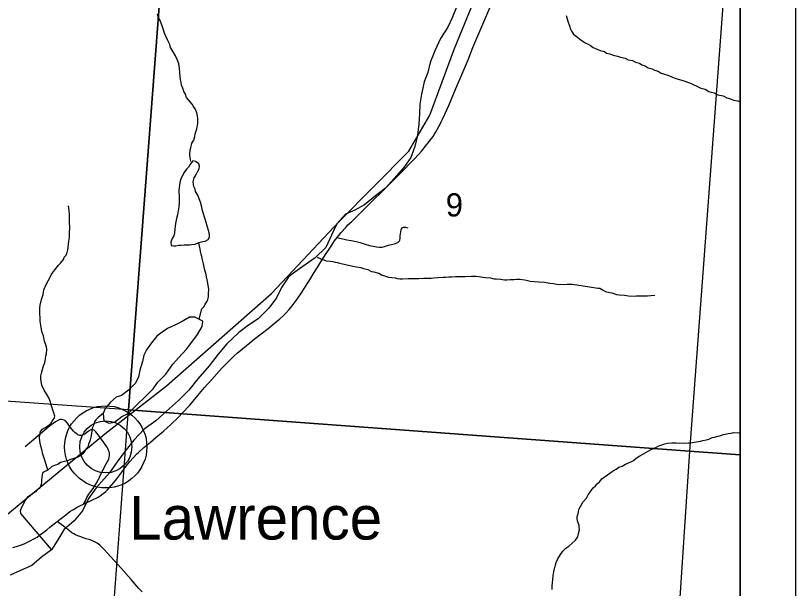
# Model space of a CAD drawing. Extents: x 0 to 82.7, y -0.2 to 22.
# Drawn here: x 7.589 to 9, y 17.868 to 18.905 of the extents above; entities that cross this region are included whole.
import ezdxf

# ---------------------------------------------------------------- set-up
doc = ezdxf.new("R2010")
doc.units = 0
for name, color, linetype in [('GM_X_County_Road', 7, 'Continuous'), ('GM_X_Minor_Lake', 7, 'Continuous'), ('GM_X_Minor_River', 7, 'Continuous'), ('GM_X_Rail_Line', 7, 'Continuous'), ('GM_X_Section', 7, 'Continuous'), ('GM_X_Section_Text', 7, 'Continuous'), ('GM_X_State_Route', 7, 'Continuous'), ('GM_X_Township_Road', 7, 'Continuous'), ('GM_X_Township_Text', 7, 'Continuous'), ('GM_X_Unincorporated', 7, 'Continuous'), ('GM_X_Unincorporated_Location', 7, 'Continuous'), ('GM_X_Unincorporated_Text', 7, 'Continuous'), ('SH_Cut_Line', 7, 'Continuous'), ('SH_Data', 7, 'Continuous')]:
    doc.layers.add(name, color=color, linetype=linetype)

msp = doc.modelspace()

# ---------------------------------------------------------------- linework, layer by layer
at = {"layer": 'GM_X_County_Road'}
for points in [[(8.9, 18.1099), (8.9, 19.1246), (8.8838, 19.1258), (8.8083, 18.1167)], [(8.9, 17.1004), (8.9, 18.1099), (8.8083, 18.1167), (8.7418, 17.1109)]]:
    msp.add_lwpolyline(points, close=True, dxfattribs=at)
at = {"layer": 'GM_X_Minor_Lake'}
for points in [[(7.9276, 18.3519), (7.9132, 18.3595), (7.9033, 18.3591), (7.8904, 18.3515), (7.8778, 18.3458), (7.8638, 18.3386), (7.8539, 18.3325), (7.8444, 18.3249), (7.8345, 18.3132), (7.8257, 18.3002), (7.8208, 18.2907), (7.8181, 18.2793), (7.8135, 18.2634), (7.8109, 18.2508), (7.8048, 18.2391), (7.793, 18.2273), (7.7804, 18.2174), (7.7706, 18.2144), (7.7603, 18.2056), (7.7508, 18.1943), (7.7474, 18.1848), (7.7481, 18.1718), (7.7576, 18.1676), (7.7679, 18.1695), (7.7808, 18.1798), (7.7926, 18.1851), (7.807, 18.1995), (7.8245, 18.2166), (7.8375, 18.2299), (7.8462, 18.2417), (7.8603, 18.2561), (7.8732, 18.274), (7.8835, 18.2858), (7.8979, 18.3013), (7.9094, 18.3165), (7.9181, 18.3283), (7.9261, 18.3424), (7.9276, 18.3519)], [(7.7603, 18.2056), (7.7508, 18.1943), (7.7474, 18.1848), (7.7481, 18.1718), (7.7576, 18.1676), (7.7679, 18.1695), (7.7808, 18.1798), (7.7926, 18.1851), (7.807, 18.1995), (7.8245, 18.2166), (7.8375, 18.2299), (7.8462, 18.2417), (7.8603, 18.2561), (7.8732, 18.274), (7.8835, 18.2858), (7.8979, 18.3013), (7.9094, 18.3165), (7.9181, 18.3283), (7.9261, 18.3424), (7.9276, 18.3519)], [(7.9276, 18.3519), (7.9132, 18.3595), (7.9033, 18.3591), (7.8904, 18.3515), (7.8778, 18.3458), (7.8638, 18.3386), (7.8539, 18.3325), (7.8444, 18.3249), (7.8345, 18.3132), (7.8257, 18.3002), (7.8208, 18.2907), (7.8181, 18.2793), (7.8135, 18.2634), (7.8109, 18.2508), (7.8048, 18.2391), (7.793, 18.2273), (7.7804, 18.2174), (7.7706, 18.2144), (7.7603, 18.2056)]]:
    msp.add_lwpolyline(points, dxfattribs=at)
at = {"layer": 'GM_X_Minor_River'}
for points in [[(8.3867, 18.9205), (8.3786, 18.9016), (8.3709, 18.8845), (8.3579, 18.8641), (8.3475, 18.8417), (8.3387, 18.8205), (8.3348, 18.8027), (8.3282, 18.7856), (8.3231, 18.7629), (8.3203, 18.7451), (8.3198, 18.7276), (8.3186, 18.7097), (8.3158, 18.6881), (8.3115, 18.6684), (8.3038, 18.6487), (8.2911, 18.6305), (8.2739, 18.6105), (8.2579, 18.5931), (8.24, 18.5792), (8.2201, 18.5629), (8.2026, 18.5532), (8.1855, 18.546), (8.1702, 18.5286), (8.1606, 18.5078), (8.1502, 18.4858), (8.1311, 18.4666), (8.1022, 18.447), (8.0831, 18.433), (8.0701, 18.413), (8.0609, 18.3944), (8.0471, 18.3755), (8.0276, 18.3566), (8.0101, 18.3449), (7.9926, 18.3314), (7.9712, 18.3114), (7.9555, 18.2921), (7.9387, 18.2713), (7.9184, 18.2478), (7.902, 18.2274), (7.8837, 18.2082), (7.8619, 18.1889), (7.8425, 18.1719), (7.8215, 18.1565), (7.8024, 18.1368), (7.7887, 18.1194), (7.7737, 18.099), (7.7588, 18.0778), (7.7347, 18.0502), (7.7206, 18.0309), (7.7098, 18.0086), (7.6949, 17.9904), (7.6762, 17.9742), (7.6651, 17.956), (7.6536, 17.9379), (7.6353, 17.925), (7.6181, 17.9099), (7.5976, 17.9006), (7.5789, 17.8923)], [(7.906, 18.6412), (7.9046, 18.6484), (7.9039, 18.6533), (7.9043, 18.6621), (7.9059, 18.6659), (7.9079, 18.6742), (7.911, 18.6802), (7.913, 18.6863), (7.9138, 18.6912), (7.9165, 18.7003), (7.9182, 18.7102), (7.9186, 18.7147), (7.9187, 18.7197), (7.9179, 18.7235), (7.9169, 18.7296), (7.9135, 18.7368), (7.9106, 18.7407), (7.908, 18.7452), (7.9016, 18.7529), (7.8978, 18.7572), (7.896, 18.7629), (7.8934, 18.7682), (7.8916, 18.774), (7.889, 18.7797), (7.8883, 18.7842), (7.8868, 18.79), (7.8865, 18.7953), (7.8858, 18.8018), (7.8852, 18.8101), (7.8841, 18.8181), (7.8812, 18.8258), (7.8779, 18.8326), (7.8738, 18.8399), (7.8689, 18.8479), (7.8675, 18.8533), (7.8638, 18.8617), (7.8604, 18.8682), (7.8582, 18.8735), (7.856, 18.8815), (7.852, 18.8915), (7.8498, 18.8976), (7.8475, 18.9014), (7.8457, 18.9083)], [(8.5851, 18.9057), (8.5884, 18.8954), (8.5913, 18.887), (8.5928, 18.8809), (8.5946, 18.8771), (8.5984, 18.8721), (8.6055, 18.8663), (8.61, 18.8625), (8.6194, 18.8563), (8.6251, 18.8535), (8.6292, 18.8516), (8.6341, 18.8477), (8.6383, 18.8458), (8.6466, 18.8423), (8.6542, 18.8403), (8.6583, 18.8375), (8.6644, 18.8363), (8.67, 18.8336), (8.678, 18.832), (8.6836, 18.83), (8.6916, 18.8284), (8.6976, 18.8253), (8.7052, 18.824), (8.7108, 18.8213), (8.7176, 18.8193), (8.7222, 18.8166), (8.7282, 18.8146), (8.7335, 18.8111), (8.7407, 18.8091), (8.7452, 18.8064), (8.7516, 18.8048), (8.7573, 18.8013), (8.769, 18.7978), (8.7837, 18.7915), (8.7947, 18.7887), (8.8102, 18.7832), (8.8162, 18.7801), (8.8204, 18.7781), (8.8287, 18.7738), (8.8366, 18.7722), (8.8434, 18.7679), (8.8528, 18.7655), (8.8596, 18.762), (8.8691, 18.76), (8.8759, 18.7565), (8.8827, 18.7549), (8.888, 18.7526), (8.8959, 18.7509), (8.9, 18.749)], [(7.9013, 18.6313), (7.8979, 18.6276), (7.8929, 18.6208), (7.8909, 18.6155), (7.8878, 18.6099), (7.8858, 18.603), (7.885, 18.5977), (7.8846, 18.5939), (7.8841, 18.5886), (7.8841, 18.5844), (7.8844, 18.5803), (7.8848, 18.5757), (7.8847, 18.5673), (7.8838, 18.5594), (7.883, 18.5518), (7.8817, 18.545), (7.8798, 18.5378), (7.8778, 18.5291), (7.8773, 18.5245), (7.8761, 18.512), (7.8749, 18.5067), (7.8718, 18.5018), (7.8694, 18.4953), (7.8705, 18.4889), (7.8743, 18.4884), (7.8784, 18.4888), (7.8838, 18.4895), (7.8876, 18.4898), (7.8936, 18.4901), (7.8986, 18.4904), (7.9031, 18.4904), (7.9073, 18.4907), (7.9138, 18.4917), (7.9201, 18.4945)], [(7.9201, 18.4945), (7.9229, 18.4954), (7.9275, 18.4965), (7.9316, 18.4968), (7.9374, 18.5002), (7.9393, 18.504), (7.9397, 18.5081), (7.939, 18.5123), (7.9376, 18.5161), (7.9361, 18.5226), (7.935, 18.5264), (7.9325, 18.5348), (7.9306, 18.5405), (7.9288, 18.5466), (7.9266, 18.5543), (7.9255, 18.5585), (7.923, 18.5676), (7.9208, 18.5737), (7.9182, 18.5802), (7.9145, 18.5867), (7.9134, 18.5913), (7.9112, 18.5959), (7.9104, 18.5997), (7.9101, 18.6046), (7.9117, 18.6115), (7.9156, 18.6179), (7.9179, 18.6224), (7.9206, 18.6281), (7.9215, 18.633), (7.9204, 18.6368), (7.9143, 18.6414), (7.9094, 18.6423), (7.904, 18.6351), (7.9013, 18.6313)], [(7.6469, 18.0825), (7.6421, 18.0985), (7.6399, 18.1061), (7.6381, 18.1111), (7.6359, 18.1195), (7.6345, 18.126), (7.6334, 18.1313), (7.6327, 18.1359), (7.632, 18.1401), (7.6328, 18.1476), (7.634, 18.1526), (7.6371, 18.1567), (7.6413, 18.1593), (7.647, 18.1627), (7.6524, 18.1668), (7.6551, 18.1709), (7.6586, 18.1762), (7.6594, 18.1804), (7.6576, 18.1861), (7.6561, 18.191), (7.6543, 18.1968), (7.6532, 18.2006), (7.6517, 18.2052), (7.6488, 18.2132), (7.6447, 18.2208), (7.6409, 18.2258), (7.6391, 18.2304), (7.6365, 18.2346), (7.6358, 18.2388), (7.6344, 18.2479), (7.6344, 18.2533), (7.6356, 18.2582), (7.6392, 18.2714), (7.6411, 18.2756), (7.6419, 18.2798), (7.6432, 18.2892), (7.6444, 18.293), (7.6449, 18.3014), (7.6445, 18.3056), (7.6434, 18.3094), (7.6412, 18.3162), (7.6391, 18.3254), (7.6365, 18.3315), (7.6358, 18.3368), (7.6347, 18.341), (7.6329, 18.3524), (7.6324, 18.3714), (7.6328, 18.3756), (7.6333, 18.3809), (7.6353, 18.3915), (7.6384, 18.4002), (7.64, 18.4086), (7.6439, 18.4188), (7.6478, 18.4252), (7.6497, 18.4297), (7.6532, 18.4358), (7.6559, 18.4403), (7.6598, 18.4452), (7.6625, 18.449), (7.6659, 18.4527), (7.6698, 18.4572), (7.6752, 18.464), (7.6767, 18.4678), (7.6802, 18.4715), (7.6822, 18.4764), (7.683, 18.4814), (7.6838, 18.4855), (7.6846, 18.4916), (7.685, 18.4973), (7.6859, 18.5041), (7.6863, 18.5083), (7.6865, 18.5246), (7.6862, 18.5288), (7.6863, 18.541), (7.686, 18.5459), (7.6857, 18.552), (7.685, 18.557), (7.6846, 18.5608)], [(7.921, 18.3559), (7.9257, 18.3742), (7.9299, 18.3787), (7.9315, 18.3829), (7.9349, 18.3874), (7.9365, 18.3915), (7.9377, 18.3961), (7.9378, 18.4025), (7.9382, 18.4097), (7.9368, 18.4212), (7.9354, 18.4273), (7.9343, 18.4326), (7.9329, 18.4391), (7.931, 18.4448), (7.93, 18.4501), (7.9289, 18.4558), (7.9271, 18.4631), (7.9256, 18.4692), (7.9245, 18.4734), (7.9235, 18.4783), (7.9228, 18.4829), (7.9217, 18.4878), (7.9201, 18.4945)], [(8.1347, 18.468), (8.1411, 18.4649), (8.1464, 18.4633), (8.1509, 18.4614), (8.1577, 18.4605), (8.1626, 18.4601), (8.1672, 18.4589), (8.1714, 18.4585), (8.1751, 18.4569), (8.1831, 18.4553), (8.1884, 18.4541), (8.1941, 18.4532), (8.199, 18.452), (8.2058, 18.4508), (8.2137, 18.4496), (8.2186, 18.4476), (8.2262, 18.4456), (8.233, 18.4421), (8.2372, 18.4413), (8.2459, 18.4389), (8.2511, 18.4362), (8.2636, 18.4318), (8.2754, 18.4305), (8.2791, 18.4297), (8.2841, 18.4289), (8.289, 18.4289), (8.2992, 18.4295), (8.3186, 18.4296), (8.3277, 18.4299), (8.3326, 18.4302), (8.3406, 18.4301), (8.3455, 18.4304), (8.3524, 18.4311), (8.3623, 18.4317), (8.3668, 18.4317), (8.3729, 18.4323), (8.3774, 18.4327), (8.385, 18.433), (8.393, 18.4329), (8.3983, 18.4332), (8.4025, 18.4331), (8.4139, 18.4337), (8.4222, 18.4336), (8.4271, 18.4328), (8.4343, 18.4319), (8.4393, 18.4315), (8.4484, 18.4306), (8.4548, 18.429), (8.4586, 18.4286), (8.4662, 18.4281), (8.4734, 18.4273), (8.4775, 18.4272), (8.4836, 18.4275), (8.4908, 18.4278), (8.495, 18.4281), (8.5011, 18.4281), (8.5102, 18.4268), (8.52, 18.4248), (8.5359, 18.4234), (8.5461, 18.4225), (8.5556, 18.4209), (8.562, 18.4201), (8.5681, 18.4192), (8.5727, 18.4188), (8.5867, 18.419), (8.5958, 18.4189), (8.5996, 18.4184), (8.6045, 18.418), (8.6159, 18.416), (8.6272, 18.4143), (8.6424, 18.4118), (8.6462, 18.4118), (8.6522, 18.4083), (8.6564, 18.4059), (8.6639, 18.4043), (8.6677, 18.4035), (8.6764, 18.4004), (8.6817, 18.3999), (8.6904, 18.3991), (8.698, 18.3982), (8.7079, 18.3977), (8.7116, 18.398), (8.7325, 18.3978), (8.7386, 18.3984), (8.7458, 18.3991)], [(7.7471, 18.185), (7.7417, 18.1805), (7.7379, 18.1779), (7.7344, 18.1741), (7.7314, 18.1703), (7.7294, 18.1635), (7.7274, 18.1586), (7.7266, 18.1544), (7.7258, 18.1488), (7.7246, 18.1419), (7.7234, 18.1374), (7.7222, 18.1336), (7.7206, 18.1294), (7.7191, 18.1249), (7.7164, 18.1208), (7.714, 18.1166), (7.7106, 18.1121), (7.7052, 18.1084), (7.7014, 18.1061), (7.6938, 18.1036), (7.6881, 18.1014), (7.6824, 18.0995), (7.6744, 18.0973), (7.6702, 18.0963), (7.6648, 18.0929), (7.6606, 18.0914), (7.6545, 18.0892), (7.6469, 18.0825), (7.6377, 18.0781), (7.6369, 18.0739), (7.6361, 18.069), (7.6357, 18.0648), (7.6356, 18.0606), (7.6348, 18.0561), (7.6317, 18.0493), (7.6279, 18.0466), (7.6244, 18.0429), (7.6194, 18.0392), (7.6149, 18.0366), (7.6099, 18.0332), (7.606, 18.0283), (7.6014, 18.0177), (7.5983, 18.0124), (7.5971, 18.0083), (7.5978, 18.0037), (7.6531, 17.9384)], [(8.5598, 17.8661), (8.5599, 17.8737), (8.5603, 17.8779), (8.5608, 17.8851), (8.5613, 17.8912), (8.5625, 17.898), (8.5637, 17.9037), (8.5649, 17.9086), (8.5668, 17.9154), (8.5703, 17.9219), (8.575, 17.9298), (8.5792, 17.9358), (8.5846, 17.9414), (8.5899, 17.9448), (8.5953, 17.9497), (8.6018, 17.9556), (8.6061, 17.9617), (8.6077, 17.9677), (8.6093, 17.9742), (8.6089, 17.9784), (8.6086, 17.9829), (8.6067, 17.9867), (8.6057, 17.9909), (8.6049, 17.9947), (8.605, 17.9985), (8.6066, 18.0035), (8.6074, 18.0076), (8.6089, 18.0122), (8.6113, 18.0167), (8.6155, 18.0242), (8.6217, 18.0314), (8.6248, 18.0378), (8.629, 18.0438), (8.634, 18.0502), (8.6383, 18.054), (8.6413, 18.0577), (8.6452, 18.0611), (8.6494, 18.0667), (8.6597, 18.0738), (8.6681, 18.0798), (8.672, 18.0824), (8.6758, 18.0843), (8.6804, 18.088), (8.6865, 18.0895), (8.6922, 18.0932), (8.7021, 18.0972), (8.7067, 18.0998), (8.7117, 18.1039), (8.7185, 18.1084), (8.725, 18.1118), (8.7338, 18.1166), (8.7388, 18.1199), (8.7483, 18.124), (8.7529, 18.1262), (8.7639, 18.1299), (8.7685, 18.1313), (8.7761, 18.1316), (8.7803, 18.1316), (8.7841, 18.1319), (8.7898, 18.1314), (8.7951, 18.1318), (8.7996, 18.1313), (8.8057, 18.1316), (8.8106, 18.1319), (8.8167, 18.133), (8.8209, 18.1337), (8.8281, 18.1348), (8.8327, 18.1362), (8.8391, 18.1373), (8.8433, 18.1387), (8.8491, 18.1413), (8.8536, 18.1424), (8.8601, 18.1442), (8.865, 18.1453), (8.87, 18.1471), (8.8784, 18.1486), (8.8837, 18.1496), (8.8882, 18.1503), (8.8981, 18.1502), (8.9, 18.1499)]]:
    msp.add_lwpolyline(points, dxfattribs=at)
at = {"layer": 'GM_X_Rail_Line'}
msp.add_lwpolyline([(7.3273, 17.7066), (7.335, 17.743), (7.346, 17.7746), (7.3734, 17.8206), (7.4119, 17.8691), (7.7503, 18.1483), (7.8617, 18.235), (8.0519, 18.4025), (8.1745, 18.5326), (8.3001, 18.66), (8.3381, 18.7253), (8.3827, 18.8457), (8.5197, 19.18), (8.5273, 19.1937), (8.5384, 19.2118)], dxfattribs=at)
at = {"layer": 'GM_X_Section'}
for points in [[(6.8524, 19.275), (7.8698, 19.2002), (7.7927, 18.1915), (6.7772, 18.2637)], [(7.8698, 19.2002), (8.8838, 19.1258), (8.8083, 18.1167), (7.7927, 18.1915)], [(7.7927, 18.1915), (8.8083, 18.1167), (8.7418, 17.1109), (7.7171, 17.1775)]]:
    msp.add_lwpolyline(points, close=True, dxfattribs=at)
at = {"layer": 'GM_X_State_Route'}
msp.add_lwpolyline([(7.5839, 17.9421), (7.5901, 17.9444), (7.5954, 17.9461), (7.6042, 17.9492), (7.61, 17.9517), (7.6151, 17.9541), (7.6219, 17.9579), (7.6277, 17.9613), (7.6316, 17.9645), (7.6381, 17.9691), (7.6452, 17.9742), (7.6508, 17.9791), (7.6641, 17.9895), (7.6718, 17.9954), (7.6793, 18.0013), (7.6867, 18.0073), (7.6935, 18.0112), (7.7001, 18.0152), (7.7049, 18.0177), (7.7113, 18.021), (7.7302, 18.0297), (7.7335, 18.0312), (7.7381, 18.0335), (7.7419, 18.036), (7.7473, 18.04), (7.7517, 18.0438), (7.755, 18.0469), (7.7588, 18.051), (7.7663, 18.0599), (7.7719, 18.0669), (7.7807, 18.0788), (7.7883, 18.0891), (7.7961, 18.0989), (7.8007, 18.1041), (7.8083, 18.1117), (7.8113, 18.1146), (7.8208, 18.1232), (7.8328, 18.1333), (7.8424, 18.1415), (7.8561, 18.1528), (7.8696, 18.1649), (7.8837, 18.1782), (7.891, 18.1864), (7.9038, 18.2003), (7.9183, 18.2177), (7.9308, 18.2323), (7.9431, 18.2461), (7.9621, 18.2669), (7.9739, 18.2792), (7.98, 18.2852), (7.9845, 18.2895), (7.9897, 18.2943), (7.9992, 18.3021), (8.0127, 18.313), (8.0206, 18.3193), (8.0457, 18.339), (8.0602, 18.3507), (8.0668, 18.3563), (8.0723, 18.3612), (8.0776, 18.3665), (8.0834, 18.3726), (8.084, 18.3732), (8.0893, 18.3797), (8.0931, 18.3845), (8.0983, 18.3918), (8.1073, 18.4055), (8.1166, 18.42), (8.1198, 18.4252), (8.1293, 18.4403), (8.1358, 18.4507), (8.1413, 18.4595), (8.1508, 18.4745), (8.1559, 18.4825), (8.1607, 18.49), (8.166, 18.4977), (8.1706, 18.5038), (8.1781, 18.5128), (8.1864, 18.5217), (8.1902, 18.5263), (8.1969, 18.5328), (8.2217, 18.5573), (8.2329, 18.5684), (8.2543, 18.5895), (8.2696, 18.6046), (8.2837, 18.6186), (8.3115, 18.6469), (8.3241, 18.6606), (8.3374, 18.6772), (8.3416, 18.6828), (8.3442, 18.6865), (8.3488, 18.6937), (8.3519, 18.6992), (8.3549, 18.7049), (8.3571, 18.7088), (8.3591, 18.7129), (8.3621, 18.719), (8.3725, 18.7427), (8.3854, 18.7732), (8.3986, 18.8045), (8.4075, 18.8251), (8.4164, 18.8476), (8.4893, 19.0186)], dxfattribs=at)
at = {"layer": 'GM_X_Township_Road'}
for points in [[(8.1706, 18.5038), (8.1879, 18.4996), (8.1961, 18.4982), (8.202, 18.4969), (8.2074, 18.4956), (8.2123, 18.4945), (8.2213, 18.4917), (8.229, 18.4894), (8.2416, 18.4868), (8.2465, 18.4862), (8.25, 18.4862), (8.2521, 18.4863), (8.2563, 18.4876), (8.2638, 18.4895), (8.2712, 18.4916), (8.2763, 18.493), (8.2785, 18.4937), (8.2802, 18.4949), (8.282, 18.4964), (8.2833, 18.4976), (8.2838, 18.4991), (8.2844, 18.5023), (8.2849, 18.5064), (8.286, 18.5138), (8.2866, 18.5176), (8.2873, 18.5195), (8.288, 18.5209), (8.2891, 18.5216), (8.2904, 18.5222), (8.2921, 18.5222), (8.2941, 18.5221), (8.2986, 18.5211)], [(7.7292, 18.1556), (7.7273, 18.1559), (7.7248, 18.1555), (7.7208, 18.153), (7.7139, 18.1478), (7.711, 18.1461), (7.709, 18.1452), (7.7066, 18.1449), (7.7051, 18.1452), (7.7029, 18.1459), (7.7014, 18.1464), (7.6998, 18.1474), (7.6981, 18.1486), (7.6956, 18.1508), (7.6935, 18.1532), (7.6879, 18.1599), (7.6823, 18.1676), (7.6791, 18.1714), (7.6764, 18.1729), (7.6744, 18.1736), (7.6716, 18.1743), (7.6696, 18.1742), (7.6672, 18.1736), (7.6651, 18.1725), (7.6607, 18.1697), (7.6522, 18.1639), (7.6493, 18.1615), (7.6058, 18.1243)], [(7.7113, 18.021), (7.7149, 18.0271), (7.7178, 18.0331), (7.7212, 18.039), (7.7246, 18.0437), (7.7291, 18.0493), (7.7377, 18.0633), (7.7435, 18.0766), (7.7523, 18.0937), (7.7572, 18.1022), (7.758, 18.1057), (7.7585, 18.1084), (7.7587, 18.1118), (7.7584, 18.1144), (7.7575, 18.117), (7.756, 18.1206), (7.7538, 18.1246), (7.7483, 18.1326), (7.7416, 18.1417), (7.7364, 18.1486), (7.7336, 18.152), (7.7323, 18.1535), (7.7306, 18.155), (7.7292, 18.1556)], [(7.8178, 17.8623), (7.8118, 17.8683), (7.7976, 17.8843), (7.779, 17.9053), (7.7548, 17.9319), (7.7484, 17.9393), (7.7449, 17.9432), (7.7408, 17.9467), (7.7361, 17.95), (7.7313, 17.9526), (7.7265, 17.9548), (7.7215, 17.9566), (7.7165, 17.9581), (7.7112, 17.9599), (7.7068, 17.9614), (7.7011, 17.9637), (7.6973, 17.9652), (7.6941, 17.9671), (7.6903, 17.9691), (7.6862, 17.9722), (7.68, 17.9773), (7.6641, 17.9895)]]:
    msp.add_lwpolyline(points, dxfattribs=at)
at = {"layer": 'GM_X_Township_Text'}
msp.add_lwpolyline([(8.9, 14.1), (8.9, 20.1381), (8.3897, 20.1756), (7.9434, 20.2083), (6.9227, 20.2875), (6.7144, 20.301), (6.2809, 20.329), (6.1569, 20.3371), (6.0773, 20.3422), (5.9906, 20.3478), (5.9672, 20.3493), (3.6288, 20.5056)], dxfattribs=at)
at = {"layer": 'GM_X_Unincorporated'}
for radius in [0.0744, 0.0472]:
    msp.add_circle((7.7518, 18.1245), radius, dxfattribs=at)
at = {"layer": 'GM_X_Unincorporated_Location'}
msp.add_line((7.7518, 18.1245), (7.7518, 18.1245), dxfattribs=at)
at = {"layer": 'SH_Cut_Line'}
msp.add_lwpolyline([(8.9, 14.1), (8.9, 20.9), (6.1272, 20.9), (5.9756, 20.3782), (5.9672, 20.3493), (3.6288, 20.5056), (3.179, 20.5374), (2.884, 20.5583), (2.8651, 20.279), (2.8645, 20.2703), (2.8645, 20.2693), (2.8288, 19.7415), (2.7788, 19.0007), (2.7784, 18.9951), (2.7199, 18.1299), (3.0279, 17.3486), (3.0556, 17.2782), (3.2909, 16.7562), (3.4071, 16.476), (3.6125, 15.9807), (3.8036, 15.5496), (4.1209, 14.8338)], dxfattribs=at)
at = {"layer": 'SH_Data'}
for p, q in [((9, 21), (9, 14)), ((8.9, 20.9), (8.9, 14.1))]:
    msp.add_line(p, q, dxfattribs=at)

# ---------------------------------------------------------------- texts
at = {"layer": 'GM_X_Section_Text'}
msp.add_text('9', height=0.0419, rotation=0, dxfattribs=at).set_placement((8.3672, 18.5418))
at = {"layer": 'GM_X_Unincorporated_Text'}
msp.add_text('Lawrence', height=0.07898, rotation=0, dxfattribs=at).set_placement((7.7942, 17.9567))

doc.saveas('drawing.dxf')
